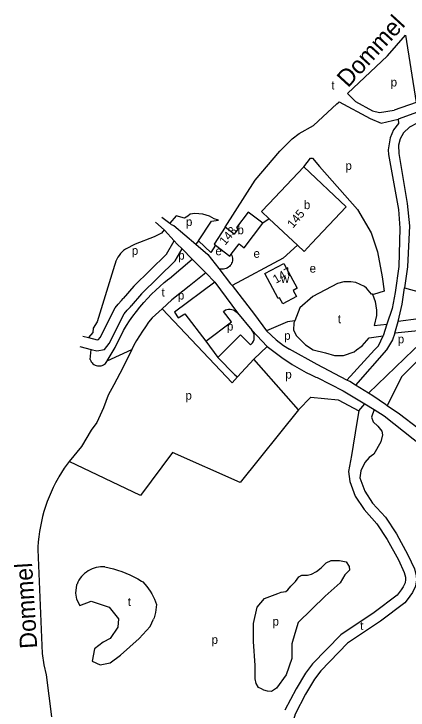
# Model space of a CAD drawing. Extents: x 160204 to 161526, y 379528 to 381793.
# Drawn here: x 160679.6 to 160862, y 381333.1 to 381655.7 of the extents above; entities that cross this region are included whole.
import ezdxf

# ---------------------------------------------------------------- set-up
doc = ezdxf.new("R2010")
doc.units = 0
for name, color, linetype in [('BLT_Basislijn', 7, 'Continuous'), ('BLT_Bebouwing', 7, 'Continuous'), ('BLT_Centroide', 7, 'Continuous'), ('BLT_Huisnummer', 7, 'Continuous'), ('BLT_Vlakafsluiter', 7, 'Continuous'), ('BLT_Waternaam_spoorwegen', 7, 'Continuous')]:
    doc.layers.add(name, color=color, linetype=linetype)

msp = doc.modelspace()

# ---------------------------------------------------------------- linework, layer by layer
at = {"layer": 'BLT_Basislijn'}
for p, q in [((160829.11, 381614.06), (160829.62, 381614.54)), ((160870.22, 381611.56), (160857.52, 381606.86)), ((160748.09, 381561.58), (160751.73, 381558.65)), ((160797.75, 381560.77), (160794.75, 381558.71)), ((160749.19, 381555.63), (160747.85, 381554.13)), ((160753.81, 381550.53), (160755.18, 381549.01)), ((160755.18, 381549.01), (160757.4, 381546.77)), ((160764.95, 381550.61), (160763.77, 381548.96)), ((160757.4, 381546.77), (160762.07, 381542.08)), ((160751.54, 381533.1), (160762.07, 381542.08)), ((160762.07, 381542.08), (160768.36, 381535.76)), ((160768.36, 381535.76), (160760.63, 381529.58)), ((160768.36, 381535.76), (160772.63, 381531.45)), ((160735.12, 381529.46), (160730.21, 381523.8)), ((160738.63, 381525.91), (160733.83, 381520.36)), ((160780.62, 381484.7), (160748.14, 381519.05)), ((160855.84, 381507.68), (160857.47, 381513.22)), ((160852.16, 381511.92), (160850.56, 381506.57)), ((160711.47, 381506.43), (160714.07, 381505.73)), ((160710.05, 381501.63), (160715.36, 381500.21)), ((160714.93, 381495.55), (160715.36, 381500.21)), ((160790.67, 381495.69), (160796.82, 381501.63)), ((160839.27, 381471.69), (160841.99, 381475.05)), ((160852.43, 381474.07), (160851.54, 381474.68)), ((160710.87, 381455.23), (160705.16, 381448.35)), ((160690.64, 381407.55), (160692.6, 381359.32))]:
    msp.add_line(p, q, dxfattribs=at)
for points in [[(160833.95, 381618.86), (160852.59, 381636.23), (160860.9, 381645.8), (160865.78, 381614.6), (160855.66, 381611.15)], [(160833.95, 381618.86), (160837.7, 381615.14), (160845.52, 381610.72), (160848.84, 381609.93), (160855.66, 381611.15)], [(160777.34, 381556.91), (160791.2, 381578.6), (160802.73, 381592.03), (160808.42, 381597.87), (160811.58, 381600.24), (160818.21, 381604.03), (160829.11, 381614.06)], [(160829.62, 381614.54), (160830.21, 381614.95), (160844.52, 381607.21), (160849.54, 381605.01), (160857.52, 381606.86)], [(160857.52, 381606.86), (160857.53, 381604.92), (160855.25, 381601.95), (160853.73, 381598.21), (160852.9, 381592.66), (160852.98, 381590.55), (160857.53, 381565.09), (160858.17, 381556.35), (160857.69, 381538.68), (160856, 381526.67), (160854.61, 381519.15), (160852.16, 381511.92)], [(160866.19, 381604.99), (160862.69, 381603.25), (160859.92, 381600.65), (160858.33, 381597.78), (160857.68, 381594.84), (160857.74, 381591.05), (160861.68, 381567.79), (160862.64, 381557.46), (160861.76, 381538.55), (160860.37, 381528.71)], [(160813.72, 381584.85), (160816.93, 381588.91), (160817.76, 381588.91), (160821.03, 381584.97), (160838.62, 381565.05), (160845.03, 381554.24), (160847.96, 381545.41), (160850.05, 381533.86), (160851.04, 381527.17), (160846.11, 381525.73), (160845.51, 381525.76)], [(160764.95, 381550.61), (160771.11, 381559.7), (160774.27, 381560.1), (160772.21, 381560.79), (160770.11, 381561.94), (160767.09, 381562.85), (160763.32, 381563.18), (160761.24, 381562.97), (160760.13, 381561.99), (160758.47, 381561.05), (160754.68, 381562.15), (160751.73, 381558.65)], [(160745.16, 381559.18), (160749.19, 381555.63)], [(160751.73, 381558.65), (160752.38, 381558.12), (160753.65, 381557.65), (160763.77, 381548.96)], [(160749.19, 381555.63), (160749.32, 381555.52), (160753.81, 381550.53)], [(160747.85, 381554.13), (160744.44, 381552.34), (160735.66, 381548.98), (160731.18, 381546.74)], [(160735.12, 381529.46), (160750.2, 381544.36), (160753.81, 381550.53)], [(160763.77, 381548.96), (160769.3, 381544.21), (160774.4, 381537.66)], [(160772.85, 381548.49), (160770.8, 381545.08), (160764.95, 381550.61)], [(160810.78, 381548.52), (160804.16, 381542.55), (160780.53, 381529.8)], [(160731.18, 381546.74), (160730.37, 381546.09), (160729.62, 381545.37), (160728.92, 381544.6), (160728.28, 381543.78), (160727.71, 381542.91), (160727.21, 381542.01), (160726.78, 381541.06), (160726.42, 381540.08), (160726.14, 381539.08)], [(160738.63, 381525.91), (160754.19, 381541.27), (160757.4, 381546.77)], [(160780.21, 381544.29), (160780.47, 381543.73), (160780.65, 381543.15), (160780.75, 381542.54), (160780.78, 381541.93), (160780.72, 381541.32), (160780.58, 381540.72), (160780.37, 381540.15), (160780.09, 381539.6), (160779.73, 381539.1), (160779.32, 381538.65), (160778.85, 381538.26), (160778.33, 381537.93), (160777.77, 381537.67), (160777.18, 381537.49), (160776.58, 381537.38), (160775.97, 381537.35), (160775.36, 381537.41), (160774.76, 381537.54), (160774.4, 381537.66)], [(160726.14, 381539.08), (160718.1, 381512.93), (160716.24, 381510.12), (160716.05, 381508.07), (160714.07, 381505.73)], [(160774.4, 381537.66), (160779.88, 381530.62), (160780.53, 381529.8)], [(160730.24, 381509), (160731.65, 381511.27), (160733.13, 381513.49), (160734.67, 381515.66), (160736.27, 381517.79), (160737.94, 381519.86), (160739.67, 381521.89), (160741.46, 381523.86), (160743.31, 381525.78), (160745.21, 381527.64), (160747.18, 381529.45), (160749.19, 381531.19), (160751.25, 381532.88), (160751.54, 381533.1)], [(160882.26, 381532.34), (160883.23, 381527.25), (160878.12, 381517.04), (160876.61, 381514.43), (160866.84, 381514.37), (160857.47, 381513.22)], [(160860.37, 381528.71), (160867.64, 381526.81), (160875.23, 381527.48), (160875.64, 381527.58), (160880.85, 381531.71), (160882.26, 381532.34)], [(160760.63, 381529.58), (160752.66, 381523.2), (160748.14, 381519.05)], [(160772.63, 381531.45), (160753.85, 381517.46), (160755.67, 381514.81), (160758.76, 381516.71), (160768.43, 381504.04)], [(160772.63, 381531.45), (160783.02, 381517.14)], [(160780.53, 381529.8), (160790.95, 381516.4), (160796.46, 381508.81)], [(160845.51, 381525.76), (160845.18, 381525.77), (160842.8, 381528.57), (160841.85, 381529.31), (160837.92, 381531.19), (160835.47, 381531.5), (160832.27, 381531.51), (160829.37, 381530.79), (160818.01, 381524.79), (160811.86, 381519.55), (160809.58, 381513.51)], [(160857.47, 381513.22), (160859.26, 381521.21), (160860.37, 381528.71)], [(160845.51, 381525.76), (160846.85, 381522.42), (160847.4, 381518.46), (160847.4, 381516.01), (160846.34, 381511.29), (160852.16, 381511.92)], [(160726.45, 381519.47), (160727.86, 381521.2), (160729.34, 381522.87), (160730.21, 381523.8)], [(160714.07, 381505.73), (160718.11, 381504.65), (160718.7, 381504.76), (160719.45, 381505.7), (160726.45, 381519.47)], [(160730.68, 381516.75), (160732.05, 381518.4), (160733.48, 381519.99), (160733.83, 381520.36)], [(160748.14, 381519.05), (160743.51, 381514.8)], [(160768.43, 381504.04), (160780.3, 381513.05), (160776.63, 381517.87), (160777.5, 381518.59), (160778.14, 381518.77), (160778.92, 381518.89), (160779.69, 381518.89), (160780.49, 381518.76), (160781.11, 381518.55), (160781.68, 381518.27), (160782.34, 381517.8), (160783.02, 381517.14)], [(160715.36, 381500.21), (160717.9, 381499.53), (160721.43, 381500.18), (160723.67, 381502.97), (160730.68, 381516.75)], [(160783.02, 381517.14), (160789.68, 381509.08)], [(160743.51, 381514.8), (160741.95, 381512.8), (160740.46, 381510.76), (160739.03, 381508.67), (160737.68, 381506.54), (160736.38, 381504.37), (160735.16, 381502.16), (160734.17, 381500.22)], [(160809.58, 381513.51), (160806.18, 381513.01), (160796.46, 381508.81)], [(160809.58, 381513.51), (160809.13, 381512.56), (160809, 381509.18), (160810.43, 381506.57), (160814.54, 381502.39), (160818.04, 381500), (160823.81, 381498.61), (160828.04, 381497.34), (160832.09, 381497.33), (160837.02, 381499.14), (160838.24, 381500), (160840.79, 381501.9), (160843.98, 381505.63), (160850.56, 381506.57)], [(160843.7, 381479.99), (160864.5, 381500), (160873.38, 381508.26), (160872.9, 381509.5), (160855.84, 381507.68)], [(160880.71, 381511.58), (160877.72, 381506.38), (160876.76, 381504.94), (160871.44, 381500), (160859.01, 381487.53), (160852.43, 381474.07)], [(160722.77, 381494.99), (160726.51, 381501.16), (160730.24, 381509)], [(160773.95, 381496.46), (160784.45, 381506.94), (160789.08, 381502.29), (160790.08, 381503.3), (160790.47, 381503.98), (160790.74, 381504.79), (160790.86, 381505.62), (160790.83, 381506.4), (160790.72, 381507.11), (160790.49, 381507.79), (160790.1, 381508.5), (160789.68, 381509.08)], [(160789.68, 381509.08), (160796.82, 381501.63)], [(160796.46, 381508.81), (160800.97, 381504.68), (160804.33, 381502.07), (160807.12, 381500.4)], [(160833.68, 381486.03), (160846.48, 381500), (160848.34, 381501.94), (160850.56, 381506.57)], [(160855.84, 381507.68), (160854.77, 381504.59), (160852.02, 381500), (160837.76, 381483.64)], [(160768.43, 381504.04), (160773.95, 381496.46)], [(160734.17, 381500.22), (160729.96, 381491.67), (160725.86, 381483.82), (160723.24, 381478.96), (160721, 381473.16), (160718.01, 381466.43), (160715.39, 381462.88), (160710.87, 381455.23)], [(160796.82, 381501.63), (160804.26, 381496.04), (160806.3, 381494.61), (160808.38, 381493.24), (160810.51, 381491.93), (160812.68, 381490.7), (160814.88, 381489.53), (160817.12, 381488.44), (160819.4, 381487.42), (160820.01, 381487.16)], [(160833.68, 381486.03), (160819.97, 381493.31), (160807.12, 381500.4)], [(160773.95, 381496.46), (160781.73, 381488.64), (160783.13, 381487.45)], [(160714.93, 381495.55), (160715.13, 381495.01), (160715.4, 381494.5), (160715.74, 381494.03), (160716.15, 381493.62), (160716.6, 381493.26), (160717.11, 381492.97), (160717.64, 381492.75), (160718.2, 381492.61), (160718.78, 381492.54), (160719.36, 381492.56), (160719.93, 381492.66), (160720.48, 381492.83), (160721.01, 381493.08), (160721.49, 381493.39), (160721.93, 381493.77), (160722.31, 381494.21), (160722.62, 381494.7), (160722.77, 381494.99)], [(160790.67, 381495.69), (160783.13, 381487.45)], [(160811.25, 381472.25), (160805.68, 381478.76), (160790.67, 381495.69)], [(160783.13, 381487.45), (160780.62, 381484.7)], [(160820.01, 381487.16), (160832.05, 381481.06), (160841.99, 381475.05)], [(160837.76, 381483.64), (160835.06, 381485.3), (160833.68, 381486.03)], [(160843.7, 381479.99), (160837.76, 381483.64)], [(160811.25, 381472.25), (160817.01, 381478.07), (160829.71, 381476.8), (160839.27, 381471.69)], [(160851.54, 381474.68), (160845.67, 381478.78), (160843.7, 381479.99)], [(160841.99, 381475.05), (160846.3, 381472.37)], [(160866.63, 381463.68), (160858.06, 381470.2), (160852.43, 381474.07)], [(160811.25, 381472.25), (160784.28, 381438.63), (160752.91, 381452.52), (160738.2, 381432.49), (160705.16, 381448.35)], [(160839.27, 381471.69), (160838.26, 381466.31), (160835.86, 381451.02), (160834.46, 381443.7), (160835.02, 381438.99), (160837.58, 381432.2), (160841.67, 381425.98), (160847.63, 381419.41), (160852.33, 381412.22), (160857.53, 381402.76), (160860.29, 381396.85), (160860.82, 381394.66), (160860.86, 381393.61), (160860.68, 381392.07), (160859.71, 381390.18), (160858.79, 381388.8), (160856.95, 381386.35), (160846.33, 381378.35), (160830.85, 381367.92), (160817.83, 381354.56), (160814.54, 381350.18), (160810.2, 381342.95), (160805.03, 381333.02)], [(160846.3, 381472.37), (160845.09, 381468.85), (160845.88, 381466.72), (160848.1, 381464.62), (160849.88, 381462.4), (160850.13, 381460.7), (160849.44, 381457.34), (160846.24, 381451.76), (160844.05, 381450.2), (160841.98, 381447.77), (160840.12, 381443.94), (160839.7, 381440.75), (160842.06, 381434.49), (160845.64, 381429.05), (160851.6, 381422.47), (160856.62, 381414.8), (160861.99, 381405.02), (160865.02, 381398.52), (160865.8, 381395.36), (160865.88, 381393.4), (160865.53, 381390.58), (160864.03, 381387.65), (160862.88, 381385.91), (160862.03, 381384.79)], [(160846.3, 381472.37), (160850.98, 381469.46), (160882.29, 381444.64), (160886.78, 381441.63), (160909.42, 381428.06), (160922.24, 381418.17), (160929, 381410.64), (160936.99, 381401.05), (160950.62, 381383.48), (160961.87, 381368.47), (160963.41, 381366.04)], [(160705.16, 381448.35), (160704.24, 381447.13), (160702.87, 381445.17), (160701.56, 381443.16), (160700.32, 381441.11), (160700, 381440.54)], [(160700, 381440.54), (160698.85, 381438.44), (160697.77, 381436.3), (160696.76, 381434.13), (160695.83, 381431.92), (160694.97, 381429.69), (160694.18, 381427.42), (160693.47, 381425.14), (160692.84, 381422.82), (160692.28, 381420.49), (160691.81, 381418.14), (160691.41, 381415.78), (160691.09, 381413.41), (160690.85, 381411.02), (160690.69, 381408.63), (160690.64, 381407.55)], [(160721.72, 381399.46), (160720.71, 381399.5), (160719.69, 381399.46), (160718.69, 381399.34), (160717.69, 381399.15), (160716.71, 381398.87), (160715.76, 381398.52), (160714.84, 381398.09), (160713.96, 381397.6), (160713.11, 381397.03), (160712.32, 381396.4), (160711.57, 381395.71), (160710.88, 381394.96), (160710.26, 381394.17), (160709.7, 381393.32), (160709.2, 381392.43), (160708.78, 381391.51), (160708.62, 381391.09)], [(160721.72, 381399.46), (160723.7, 381399.03), (160725.66, 381398.52), (160727.6, 381397.93), (160729.52, 381397.27), (160731.4, 381396.53), (160733.26, 381395.72), (160735.08, 381394.84), (160736.87, 381393.88), (160738.61, 381392.85), (160739.22, 381392.47)], [(160708.62, 381391.09), (160708.01, 381387.21), (160708.61, 381384.57), (160710.15, 381381.55), (160715.27, 381383.58), (160723.6, 381380.75), (160727.96, 381375.33), (160727.73, 381371.49), (160724.15, 381366.2), (160720.83, 381364.54), (160716.95, 381361.49), (160715.85, 381355.7), (160719.53, 381354), (160724.2, 381355.02), (160728.96, 381358.49), (160737.55, 381366.25), (160742.59, 381371.8), (160744.22, 381375.22)], [(160739.22, 381392.47), (160740.19, 381391.48), (160741.09, 381390.43), (160741.94, 381389.34), (160742.71, 381388.19), (160743.43, 381387), (160744.07, 381385.77), (160744.64, 381384.51), (160745.14, 381383.22), (160745.52, 381382.04)], [(160862.03, 381384.79), (160860.51, 381382.78), (160849.23, 381374.28), (160834.07, 381364.06), (160821.63, 381351.29), (160818.69, 381347.38), (160814.56, 381340.51), (160809.71, 381331.18), (160808.12, 381325.43), (160806.85, 381317.3), (160805.81, 381312.89), (160804.26, 381309.55), (160802.15, 381306.98), (160799.53, 381303.22), (160798.63, 381300.97), (160798.38, 381298.43), (160798.13, 381297.69)], [(160745.52, 381382.04), (160745.46, 381380.77), (160745.32, 381379.5), (160745.1, 381378.25), (160744.8, 381377.01), (160744.43, 381375.8), (160744.22, 381375.22)], [(160692.6, 381359.32), (160693.35, 381354.09), (160694.47, 381349.41), (160696.9, 381329.97)]]:
    msp.add_lwpolyline(points, dxfattribs=at)
msp.add_lwpolyline([(160792.22, 381380.76), (160795.61, 381384.87), (160801.68, 381387.19), (160803.29, 381387.73), (160805.43, 381388.08), (160806.33, 381388.8), (160807.76, 381390.58), (160809.9, 381392.73), (160811.51, 381394.87), (160812.93, 381395.58), (160815.43, 381395.58), (160817.4, 381396.12), (160819.72, 381397.37), (160821.81, 381398.97), (160824.18, 381401.3), (160826.5, 381402.37), (160830.25, 381402.37), (160833.33, 381401.79), (160834.72, 381399.69), (160834.9, 381397.9), (160832.75, 381395.76), (160830.61, 381392.01), (160823.65, 381385.94), (160811.15, 381373.62), (160809.54, 381368.62), (160808.29, 381363.8), (160808.29, 381357.01), (160805.61, 381349.51), (160801.15, 381343.27), (160798.83, 381341.66), (160797.04, 381341.84), (160795.26, 381342.37), (160794.18, 381342.91), (160792.76, 381343.62), (160791.68, 381345.41), (160791.33, 381347.55), (160791.33, 381353.8), (160790.43, 381364.87), (160790.43, 381373.26)], close=True, dxfattribs=at)
at = {"layer": 'BLT_Bebouwing'}
for p, q in [((160797.75, 381560.77), (160810.78, 381548.52)), ((160772.85, 381548.49), (160779.54, 381543.4)), ((160779.54, 381543.4), (160780.21, 381544.29))]:
    msp.add_line(p, q, dxfattribs=at)
for points in [[(160813.72, 381584.85), (160797.63, 381567.75), (160794.21, 381564.11), (160797.75, 381560.77)], [(160810.78, 381548.52), (160813.87, 381545.61), (160817.3, 381549.25), (160833.39, 381566.35), (160813.72, 381584.85)], [(160794.75, 381558.71), (160788.06, 381563.8), (160782.59, 381556.66), (160783.3, 381556.01), (160781.55, 381553.7), (160777.34, 381556.91)], [(160780.21, 381544.29), (160783.87, 381549.09), (160786.12, 381547.37), (160794.75, 381558.71)], [(160777.34, 381556.91), (160772.27, 381548.93), (160772.85, 381548.49)], [(160795.72, 381535.33), (160804.52, 381540.03), (160810.65, 381528.57), (160808.82, 381527.59), (160810.36, 381524.72), (160803.99, 381521.31), (160802.45, 381524.18), (160801.85, 381523.86), (160795.72, 381535.33)]]:
    msp.add_lwpolyline(points, dxfattribs=at)
at = {"layer": 'BLT_Vlakafsluiter'}
msp.add_line((160722.77, 381494.99), (160734.17, 381500.22), dxfattribs=at)

# ---------------------------------------------------------------- texts
at = {"layer": 'BLT_Centroide'}
for s, p in [('t', (160826.51, 381620.67)), ('p', (160853.98, 381622.07)), ('p', (160833.03, 381583.4)), ('b', (160813.8, 381565.23)), ('p', (160759.21, 381557.38)), ('b', (160783.05, 381553.59)), ('p', (160734.13, 381544.05)), ('p', (160755.62, 381541.84)), ('e', (160772.84, 381543.86)), ('e', (160790.48, 381542.69)), ('e', (160816.45, 381535.81)), ('w', (160803.19, 381531.06)), ('t', (160747.91, 381524.75)), ('p', (160755.48, 381523.33)), ('t', (160829.51, 381512.34)), ('p', (160778.19, 381508.96)), ('p', (160804.67, 381504.66)), ('p', (160857.25, 381503.05)), ('p', (160805.22, 381486.7)), ('p', (160758.96, 381476.94)), ('t', (160732.29, 381381.33)), ('p', (160799.28, 381372.25)), ('t', (160839.89, 381370.18)), ('p', (160771.09, 381363.78))]:
    msp.add_text(s, height=4, dxfattribs=at).set_placement(p)
at = {"layer": 'BLT_Huisnummer'}
for s, rotation, p in [('145', 50, (160808.74, 381556.12)), ('143', 50, (160777.34, 381548.21)), ('147', 30, (160800.86, 381530.6))]:
    msp.add_text(s, height=4, rotation=rotation, dxfattribs=at).set_placement(p)
at = {"layer": 'BLT_Waternaam_spoorwegen'}
for rotation, p in [(47.4785, (160834.22, 381621.16)), (93.5336, (160690.4, 381361.81))]:
    msp.add_text('Dommel', height=8, rotation=rotation, dxfattribs=at).set_placement(p)

doc.saveas('drawing.dxf')
